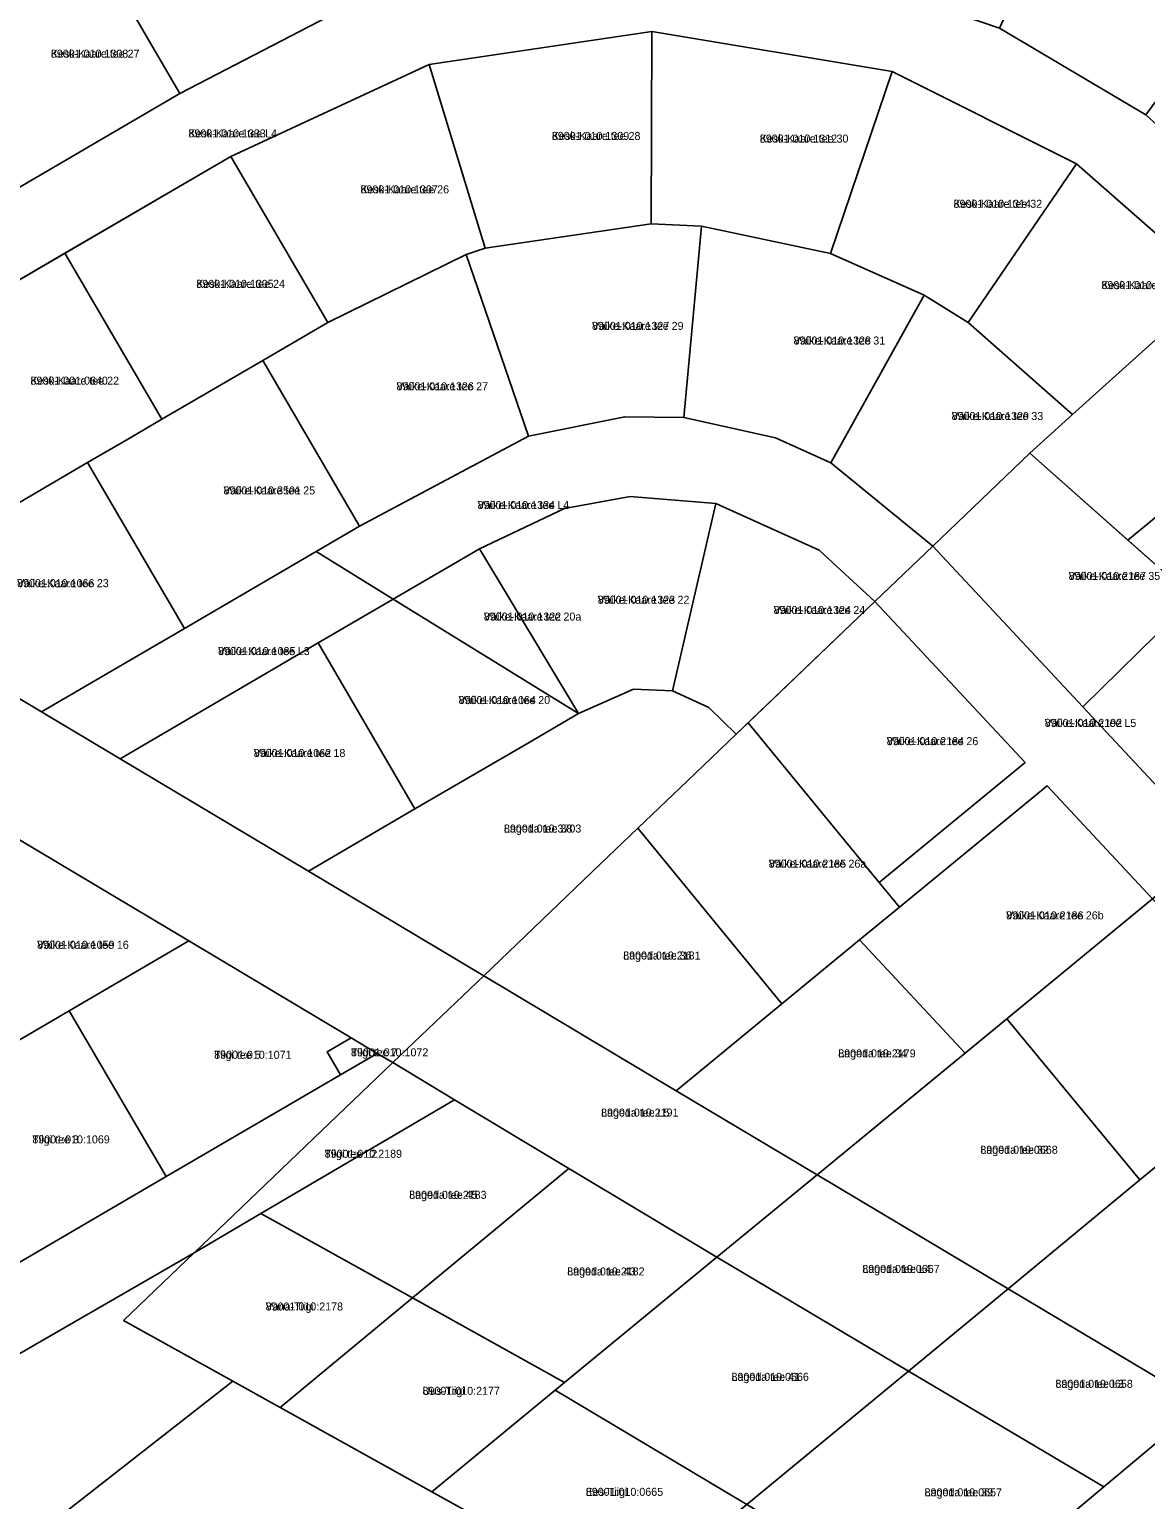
# Model space of a CAD drawing. Extents: x 526849 to 562296, y 6591741 to 6618546.
# Drawn here: x 548330.1 to 548539.4, y 6596665.2 to 6596940.7 of the extents above; entities that cross this region are included whole.
import ezdxf

# ---------------------------------------------------------------- set-up
doc = ezdxf.new("R2010")
doc.units = 0
for name, color, linetype in [('L_AADRESS', 7, 'Continuous'), ('PIIR', 7, 'Continuous'), ('TUNNUS', 7, 'Continuous')]:
    doc.layers.add(name, color=color, linetype=linetype)

msp = doc.modelspace()

# ---------------------------------------------------------------- linework, layer by layer
at = {"layer": 'PIIR'}
for points in [[(548340.22, 6596959.74), (548354.24, 6596967.81), (548374.12, 6596976.85), (548387.76, 6596943.88), (548358.36, 6596928.64)], [(548527.03, 6596973.58), (548538.19, 6596968), (548560.79, 6596953.66), (548539.44, 6596924.68), (548511.98, 6596940.88)], [(548309.99, 6596942.1), (548324.03, 6596950.29), (548340.22, 6596959.74), (548358.36, 6596928.64), (548328.12, 6596911)], [(548299.97, 6596894.58), (548328.12, 6596911), (548358.36, 6596928.64), (548387.76, 6596943.88), (548418.39, 6596952.73), (548450.18, 6596955.2), (548481.81, 6596951.2), (548511.98, 6596940.88), (548539.44, 6596924.68), (548563.62, 6596902.65), (548552.48, 6596892.61), (548526.47, 6596915.49), (548491.86, 6596932.76), (548446.84, 6596940.25), (548405.11, 6596934.11), (548367.93, 6596916.86), (548336.83, 6596898.72), (548314.44, 6596885.66)], [(548405.11, 6596934.11), (548446.84, 6596940.25), (548446.73, 6596904.25), (548415.58, 6596899.67)], [(548446.84, 6596940.25), (548491.86, 6596932.76), (548480.32, 6596898.66), (548456.13, 6596903.8), (548446.73, 6596904.25)], [(548367.93, 6596916.86), (548405.11, 6596934.11), (548415.58, 6596899.67), (548412.02, 6596898.51), (548386.07, 6596885.76)], [(548491.86, 6596932.76), (548526.47, 6596915.49), (548506.15, 6596885.77), (548497.87, 6596890.89), (548480.32, 6596898.66)], [(548336.82, 6596898.72), (548367.93, 6596916.86), (548386.07, 6596885.76), (548373.88, 6596878.65), (548354.97, 6596867.63)], [(548526.47, 6596915.49), (548552.48, 6596892.61), (548525.69, 6596868.52), (548506.15, 6596885.77)], [(548412.02, 6596898.51), (548415.58, 6596899.67), (548446.73, 6596904.25), (548456.13, 6596903.8), (548452.82, 6596867.95), (548441.77, 6596868.09), (548423.7, 6596864.46)], [(548456.13, 6596903.8), (548480.32, 6596898.66), (548497.87, 6596890.89), (548480.37, 6596859.43), (548470.02, 6596864.13), (548452.82, 6596867.95)], [(548314.44, 6596885.66), (548336.82, 6596898.72), (548354.97, 6596867.63), (548349.16, 6596864.22), (548341.05, 6596859.5), (548323.88, 6596849.47), (548305.73, 6596880.58)], [(548373.88, 6596878.65), (548386.07, 6596885.76), (548412.02, 6596898.51), (548423.7, 6596864.46), (548392.02, 6596847.56)], [(548497.87, 6596890.89), (548506.15, 6596885.77), (548525.69, 6596868.52), (548517.7, 6596861.27), (548499.49, 6596843.85), (548480.37, 6596859.43)], [(548517.7, 6596861.27), (548525.69, 6596868.52), (548552.48, 6596892.61), (548570.52, 6596873.29), (548536.09, 6596844.96)], [(548341.05, 6596859.5), (548349.16, 6596864.22), (548354.97, 6596867.63), (548373.88, 6596878.65), (548392.02, 6596847.56), (548383.89, 6596842.82), (548359.2, 6596828.41)], [(548536.09, 6596844.96), (548570.52, 6596873.29), (548588.71, 6596853.81), (548556.23, 6596827.09), (548548.37, 6596834.07)], [(548383.89, 6596842.82), (548392.02, 6596847.56), (548423.7, 6596864.46), (548441.77, 6596868.09), (548452.82, 6596867.95), (548470.02, 6596864.13), (548480.37, 6596859.43), (548499.49, 6596843.85), (548488.65, 6596833.48), (548478.21, 6596843.08), (548458.86, 6596851.81), (548442.78, 6596853.13), (548430.49, 6596850.89), (548414.53, 6596843.32), (548398.37, 6596833.89)], [(548517.7, 6596861.27), (548548.37, 6596834.07), (548527.61, 6596813.74), (548499.49, 6596843.85)], [(548297.1, 6596833.87), (548323.88, 6596849.47), (548341.05, 6596859.5), (548359.2, 6596828.41), (548332.42, 6596812.79)], [(548414.53, 6596843.32), (548430.49, 6596850.89), (548442.78, 6596853.13), (548458.86, 6596851.81), (548450.68, 6596816.75), (548443.42, 6596817.01), (548433.09, 6596812.47)], [(548458.86, 6596851.81), (548478.21, 6596843.08), (548488.65, 6596833.48), (548462.65, 6596808.6), (548457.54, 6596813.6), (548450.68, 6596816.75)], [(548499.49, 6596843.85), (548527.61, 6596813.74), (548552.32, 6596787.29), (548540.71, 6596777.74), (548520.92, 6596798.93), (548493.28, 6596776.21), (548489.47, 6596780.84), (548516.82, 6596803.32), (548488.65, 6596833.48)], [(548332.42, 6596812.79), (548359.2, 6596828.41), (548383.89, 6596842.82), (548398.37, 6596833.89), (548384.3, 6596825.69), (548347.14, 6596804.01)], [(548398.37, 6596833.89), (548414.53, 6596843.32), (548433.09, 6596812.47)], [(548384.3, 6596825.69), (548398.37, 6596833.89), (548433.09, 6596812.47), (548423.83, 6596807.07), (548402.43, 6596794.59)], [(548488.65, 6596833.48), (548516.82, 6596803.32), (548489.47, 6596780.84), (548464.89, 6596810.75)], [(548548.37, 6596834.07), (548556.23, 6596827.09), (548577.64, 6596808.1), (548552.32, 6596787.29), (548527.61, 6596813.74)], [(548347.14, 6596804.01), (548384.3, 6596825.69), (548402.43, 6596794.59), (548382.46, 6596782.94)], [(548382.46, 6596782.94), (548402.43, 6596794.59), (548423.83, 6596807.07), (548433.09, 6596812.47), (548443.42, 6596817.01), (548450.68, 6596816.75), (548457.54, 6596813.6), (548462.65, 6596808.6), (548453.52, 6596799.87), (548444.21, 6596790.97), (548437.16, 6596784.22), (548415.32, 6596763.33)], [(548464.89, 6596810.75), (548489.47, 6596780.84), (548493.28, 6596776.21), (548485.77, 6596770.04), (548471.23, 6596758.09), (548444.21, 6596790.97), (548453.52, 6596799.87), (548462.65, 6596808.6)], [(548520.92, 6596798.93), (548540.71, 6596777.74), (548513.36, 6596755.26), (548505.55, 6596748.86), (548485.77, 6596770.04), (548493.28, 6596776.21)], [(548300.71, 6596776.93), (548324.73, 6596790.94), (548360.05, 6596769.87), (548337.62, 6596756.79), (548318.85, 6596745.84)], [(548444.21, 6596790.97), (548471.23, 6596758.09), (548451.41, 6596741.8), (548415.32, 6596763.33), (548437.16, 6596784.22)], [(548567.44, 6596749.13), (548543.86, 6596729.67), (548538.29, 6596725.07), (548513.36, 6596755.26), (548540.71, 6596777.74)], [(548337.62, 6596756.79), (548360.05, 6596769.87), (548390.47, 6596751.72), (548385.94, 6596749.08), (548388.46, 6596744.76), (548355.76, 6596725.69)], [(548485.77, 6596770.04), (548505.55, 6596748.86), (548477.82, 6596726.04), (548451.41, 6596741.8), (548471.23, 6596758.09)], [(548415.32, 6596763.33), (548451.41, 6596741.8), (548477.82, 6596726.04), (548459.01, 6596710.58), (548431.29, 6596727.23), (548409.85, 6596740.11), (548398.3, 6596747.05)], [(548305.66, 6596738.14), (548318.85, 6596745.84), (548337.62, 6596756.79), (548355.76, 6596725.69), (548323.8, 6596707.05)], [(548538.29, 6596725.07), (548513.61, 6596704.69), (548477.82, 6596726.04), (548513.36, 6596755.26)], [(548385.94, 6596749.08), (548390.47, 6596751.72), (548395.37, 6596748.79), (548388.46, 6596744.76)], [(548398.3, 6596747.05), (548409.85, 6596740.11), (548373.56, 6596718.77), (548361.03, 6596711.4)], [(548409.85, 6596740.11), (548431.29, 6596727.23), (548401.98, 6596702.97), (548373.56, 6596718.77)], [(548569.14, 6596699.05), (548549.98, 6596682.99), (548513.61, 6596704.69), (548538.29, 6596725.07), (548543.86, 6596729.67)], [(548431.29, 6596727.23), (548459.01, 6596710.58), (548430.48, 6596687.13), (548401.98, 6596702.97)], [(548513.61, 6596704.69), (548494.93, 6596689.27), (548459.01, 6596710.58), (548477.82, 6596726.04)], [(548361.03, 6596711.4), (548373.56, 6596718.77), (548401.98, 6596702.97), (548377.17, 6596682.44), (548368.31, 6596687.37), (548347.82, 6596698.76)], [(548494.93, 6596689.27), (548464.65, 6596664.28), (548428.74, 6596685.7), (548459.01, 6596710.58)], [(548549.98, 6596682.99), (548531.55, 6596667.55), (548494.93, 6596689.27), (548513.61, 6596704.69)], [(548401.98, 6596702.97), (548430.48, 6596687.13), (548428.74, 6596685.7), (548405.57, 6596666.65), (548377.17, 6596682.44)], [(548368.31, 6596687.37), (548377.17, 6596682.44), (548405.57, 6596666.65), (548442.6, 6596646.07), (548472.91, 6596629.22), (548475.26, 6596621.72), (548475.57, 6596612.76), (548470.89, 6596597.31), (548418.22, 6596567.2), (548403.92, 6596563.5), (548389.62, 6596559.8), (548348.26, 6596551.46), (548323.75, 6596543.81), (548283.5, 6596533.8), (548273.07, 6596533.59), (548271.66, 6596527.46), (548268.13, 6596528.07), (548269.06, 6596533.99), (548255.92, 6596545.24), (548251.03, 6596561.95), (548253.99, 6596565.24), (548315.24, 6596645.96)], [(548531.55, 6596667.55), (548501.45, 6596642.32), (548464.65, 6596664.28), (548494.93, 6596689.27)], [(548428.74, 6596685.7), (548464.65, 6596664.28), (548448.6, 6596651.03), (548442.6, 6596646.07), (548405.57, 6596666.65)], [(548491.4, 6596633.9), (548501.45, 6596642.32), (548531.55, 6596667.55), (548549.98, 6596682.99), (548585.19, 6596661.99), (548616.1, 6596643.54), (548635.57, 6596676.18), (548645.83, 6596664.09), (548628.98, 6596635.86), (548637.6, 6596594.08), (548620.26, 6596589.09), (548614.25, 6596618.21), (548603.4, 6596624.68), (548564.29, 6596648.02), (548540.64, 6596662.12), (548508.18, 6596634.91), (548497.83, 6596626.24)]]:
    msp.add_lwpolyline(points, close=True, dxfattribs=at)
for points in [[(548297.1, 6596833.87), (548332.42, 6596812.79), (548347.14, 6596804.01), (548382.46, 6596782.94), (548415.32, 6596763.33), (548398.3, 6596747.05), (548395.37, 6596748.79), (548390.47, 6596751.72), (548360.05, 6596769.87), (548324.73, 6596790.94)], [(548323.8, 6596707.05), (548355.76, 6596725.69), (548388.46, 6596744.76), (548395.37, 6596748.79), (548398.3, 6596747.05), (548361.03, 6596711.4), (548323.44, 6596689.75)], [(548323.44, 6596689.75), (548361.03, 6596711.4), (548347.82, 6596698.76), (548368.31, 6596687.37), (548315.24, 6596645.96)]]:
    msp.add_lwpolyline(points, dxfattribs=at)

# ---------------------------------------------------------------- texts
at = {"layer": 'L_AADRESS'}
for s, p in [('Kesk-Kaare tee 27', (548334.18, 6596935.37)), ('Kesk-Kaare tee L4', (548359.96, 6596920.43)), ('Kesk-Kaare tee 28', (548428.09, 6596919.96)), ('Kesk-Kaare tee 30', (548467.07, 6596919.46)), ('Kesk-Kaare tee 26', (548392.21, 6596909.94)), ('Kesk-Kaare tee 32', (548503.39, 6596907.24)), ('Kesk-Kaare tee 24', (548361.44, 6596892.24)), ('Kesk-Kaare tee 34', (548531.11, 6596892)), ('Väike-Kaare tee 29', (548435.61, 6596884.36)), ('Väike-Kaare tee 31', (548473.4, 6596881.62)), ('Kesk-Kaare tee 22', (548330.35, 6596874.1)), ('Väike-Kaare tee 27', (548398.96, 6596873.04)), ('Väike-Kaare tee 33', (548503.03, 6596867.47)), ('Väike-Kaare tee 25', (548366.54, 6596853.53)), ('Väike-Kaare tee L4', (548414.17, 6596850.79)), ('Väike-Kaare tee 35', (548524.96, 6596837.5)), ('Väike-Kaare tee 23', (548327.84, 6596836.15)), ('Väike-Kaare tee 22', (548436.7, 6596833.04)), ('Väike-Kaare tee 20a', (548415.33, 6596829.89)), ('Väike-Kaare tee 24', (548469.66, 6596831.12)), ('Väike-Kaare tee L3', (548365.52, 6596823.42)), ('Väike-Kaare tee 20', (548410.6, 6596814.24)), ('Väike-Kaare tee L5', (548520.48, 6596809.97)), ('Väike-Kaare tee 26', (548490.86, 6596806.55)), ('Väike-Kaare tee 18', (548372.21, 6596804.32)), ('Lageda tee 38', (548419.11, 6596790.17)), ('Väike-Kaare tee 26a', (548468.75, 6596783.59)), ('Väike-Kaare tee 26b', (548513.25, 6596773.9)), ('Väike-Kaare tee 16', (548331.6, 6596768.39)), ('Lageda tee 36', (548441.46, 6596766.38)), ('Tiigi tee 5', (548364.79, 6596747.78)), ('Tiigi tee 7', (548390.43, 6596748.24)), ('Lageda tee 34', (548481.78, 6596748.04)), ('Lageda tee L5', (548437.32, 6596736.95)), ('Tiigi tee 3', (548330.71, 6596731.92)), ('Lageda tee 32', (548508.42, 6596729.98)), ('Tiigi tee L2', (548385.5, 6596729.23)), ('Lageda tee 45', (548401.34, 6596721.54)), ('Lageda tee L4', (548486.29, 6596707.65)), ('Lageda tee 43', (548430.97, 6596707.18)), ('Vana-Tiigi', (548374.44, 6596700.61)), ('Lageda tee 41', (548461.77, 6596687.43)), ('Lageda tee L3', (548522.49, 6596686.12)), ('Uus-Tiigi', (548403.85, 6596684.81)), ('Ees-Tiigi', (548434.45, 6596665.88)), ('Lageda tee 39', (548497.97, 6596665.79))]:
    msp.add_text(s, height=1.5, dxfattribs=at).set_placement(p)
at = {"layer": 'TUNNUS'}
for s, p in [('89001:010:1308', (548334.18, 6596935.37)), ('89001:010:1333', (548359.96, 6596920.43)), ('89001:010:1309', (548428.09, 6596919.96)), ('89001:010:1312', (548467.07, 6596919.46)), ('89001:010:1307', (548392.21, 6596909.94)), ('89001:010:1314', (548503.39, 6596907.24)), ('89001:010:1305', (548361.44, 6596892.24)), ('89001:010:1316', (548531.11, 6596892)), ('89001:010:1327', (548435.61, 6596884.36)), ('89001:010:1328', (548473.4, 6596881.62)), ('89001:001:0640', (548330.35, 6596874.1)), ('89001:010:1326', (548398.96, 6596873.04)), ('89001:010:1329', (548503.03, 6596867.47)), ('89001:010:3501', (548366.54, 6596853.53)), ('89001:010:1334', (548414.17, 6596850.79)), ('89001:010:2187', (548524.96, 6596837.5)), ('89001:010:1066', (548327.84, 6596836.15)), ('89001:010:1323', (548436.7, 6596833.04)), ('89001:010:1322', (548415.33, 6596829.89)), ('89001:010:1324', (548469.66, 6596831.12)), ('89001:010:1085', (548365.52, 6596823.42)), ('89001:010:1064', (548410.6, 6596814.24)), ('89001:010:2192', (548520.48, 6596809.97)), ('89001:010:2184', (548490.86, 6596806.55)), ('89001:010:1062', (548372.21, 6596804.32)), ('89001:010:3703', (548419.11, 6596790.17)), ('89001:010:2185', (548468.75, 6596783.59)), ('89001:010:2186', (548513.25, 6596773.9)), ('89001:010:1059', (548331.6, 6596768.39)), ('89001:010:2181', (548441.46, 6596766.38)), ('89001:010:1071', (548364.79, 6596747.78)), ('89001:010:1072', (548390.43, 6596748.24)), ('89001:010:2179', (548481.78, 6596748.04)), ('89001:010:2191', (548437.32, 6596736.95)), ('89001:010:1069', (548330.71, 6596731.92)), ('89001:010:0668', (548508.42, 6596729.98)), ('89001:010:2189', (548385.5, 6596729.23)), ('89001:010:2183', (548401.34, 6596721.54)), ('89001:010:0667', (548486.29, 6596707.65)), ('89001:010:2182', (548430.97, 6596707.18)), ('89001:010:2178', (548374.44, 6596700.61)), ('89001:010:0666', (548461.77, 6596687.43)), ('89001:010:0658', (548522.49, 6596686.12)), ('89001:010:2177', (548403.85, 6596684.81)), ('89001:010:0665', (548434.45, 6596665.88)), ('89001:010:0657', (548497.97, 6596665.79))]:
    msp.add_text(s, height=1.5, dxfattribs=at).set_placement(p)

doc.saveas('drawing.dxf')
